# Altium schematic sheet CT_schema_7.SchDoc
size 398 x 378 mm
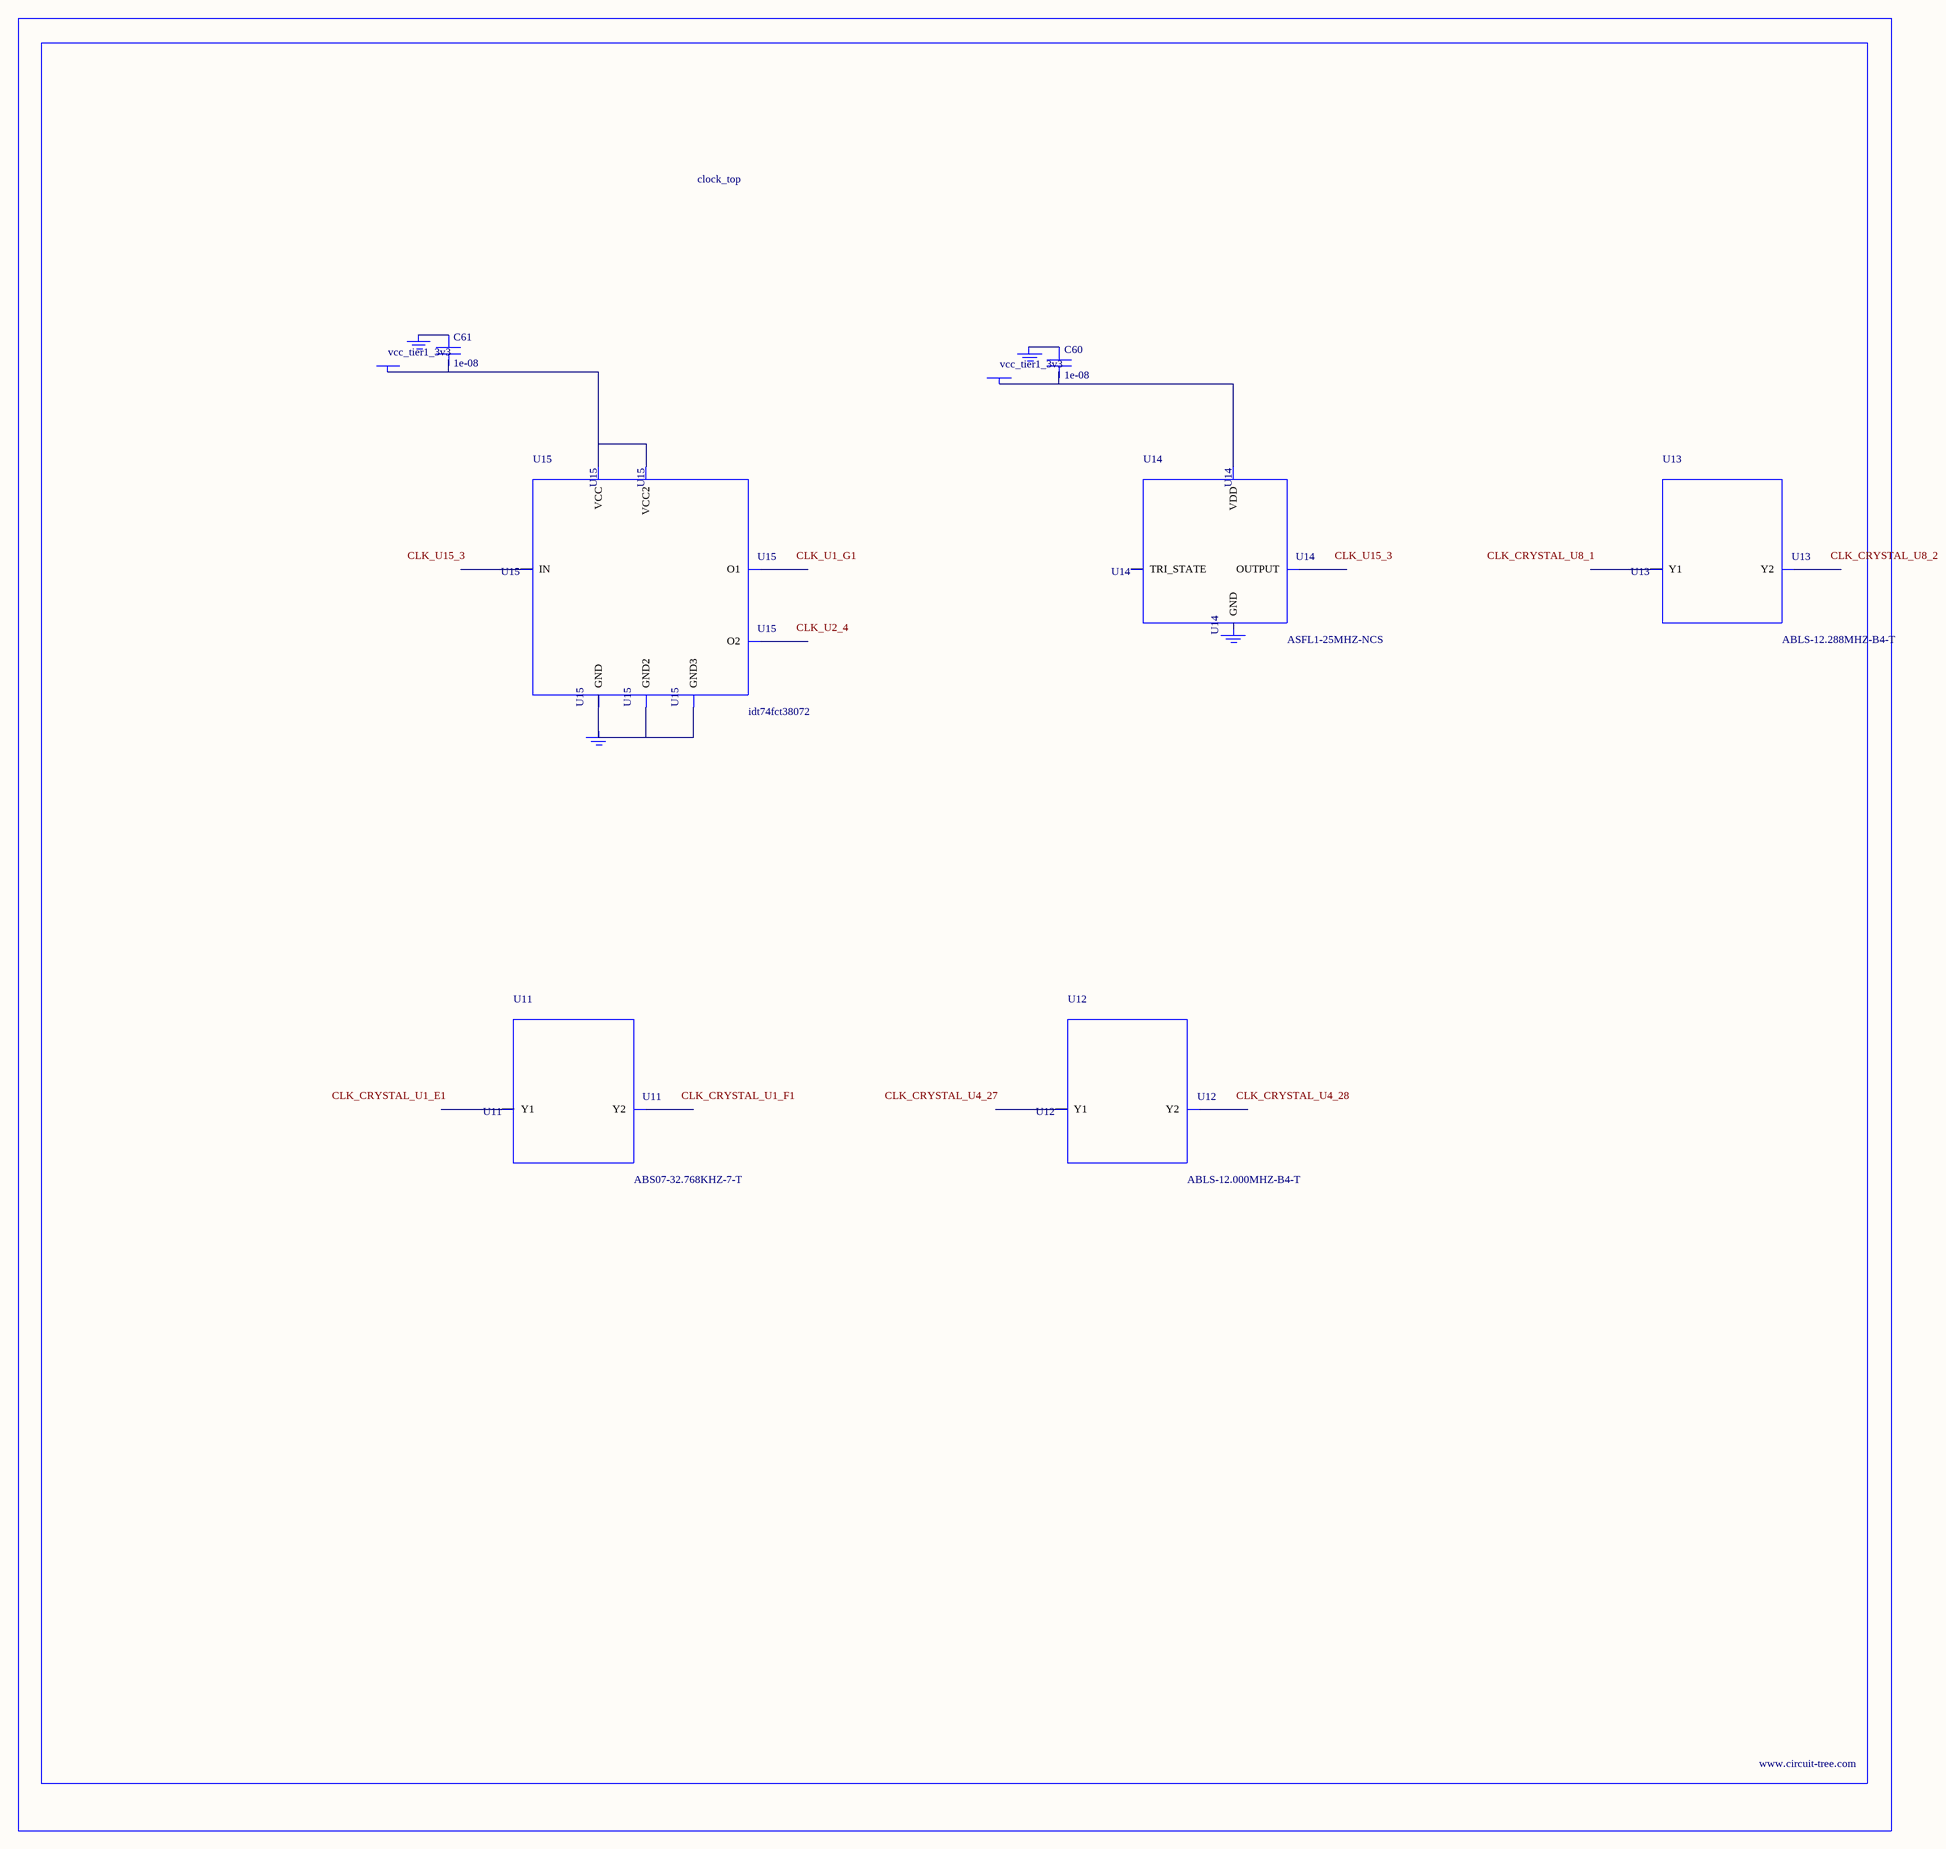
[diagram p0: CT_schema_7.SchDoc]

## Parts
BORDER6  (no value)
C60  1e-08  [C0402]
C61  1e-08  [C0402]
GND_INSTANCE_6_0  (no value)
GND_INSTANCE_6_1  (no value)
GND_INSTANCE_6_2  (no value)
GND_INSTANCE_6_3  (no value)
POWER_INSTANCE_6_0  vcc_tier1_3v3
POWER_INSTANCE_6_1  vcc_tier1_3v3
U11  ABS07-32.768KHZ-7-T  [ABS07-32.768KHZ-7-T]
U12  ABLS-12.000MHZ-B4-T  [ABLS-12.000MHZ-B4-T]
U13  ABLS-12.288MHZ-B4-T  [ABLS-12.288MHZ-B4-T]
U14  ASFL1-25MHZ-NCS  [ASFL1]
U15  idt74fct38072  [IDT74FCT38072]

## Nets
NetC60_1: C60.1 GND_INSTANCE_6_0.0(GND)
NetC60_2: C60.2 POWER_INSTANCE_6_0.0(PWR) U14.4(VDD)
NetC61_1: C61.1 GND_INSTANCE_6_2.0(GND)
NetC61_2: C61.2 POWER_INSTANCE_6_1.0(PWR) U15.1(VCC) U15.2(VCC2)
NetGND_INSTANCE_6_3_0: GND_INSTANCE_6_3.0(GND) U15.4(GND) U15.5(GND2) U15.8(GND3)

Not connected (* = marked no-connect by the designer): GND_INSTANCE_6_1 0(GND); U11 1(Y1) 2(Y2); U12 1(Y1) 2(Y2); U13 1(Y1) 2(Y2); U14 1(TRI_STATE) 2(GND) 3(OUTPUT); U15 3(IN) 6(O2) 7(O1)

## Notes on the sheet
- Labels drawn without touching a wire or pin: CLK_CRYSTAL_U1_E1, CLK_CRYSTAL_U1_F1, CLK_CRYSTAL_U4_27, CLK_CRYSTAL_U4_28, CLK_CRYSTAL_U8_1, CLK_CRYSTAL_U8_2, CLK_U1_G1, CLK_U2_4, CLK_U15_3

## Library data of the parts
BORDER6 = BORDER_PAGE6
C60 C61 = C0402C103K3RAC
GND_INSTANCE_6_0-GND_INSTANCE_6_3 = GND
POWER_INSTANCE_6_0 POWER_INSTANCE_6_1 = PWR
